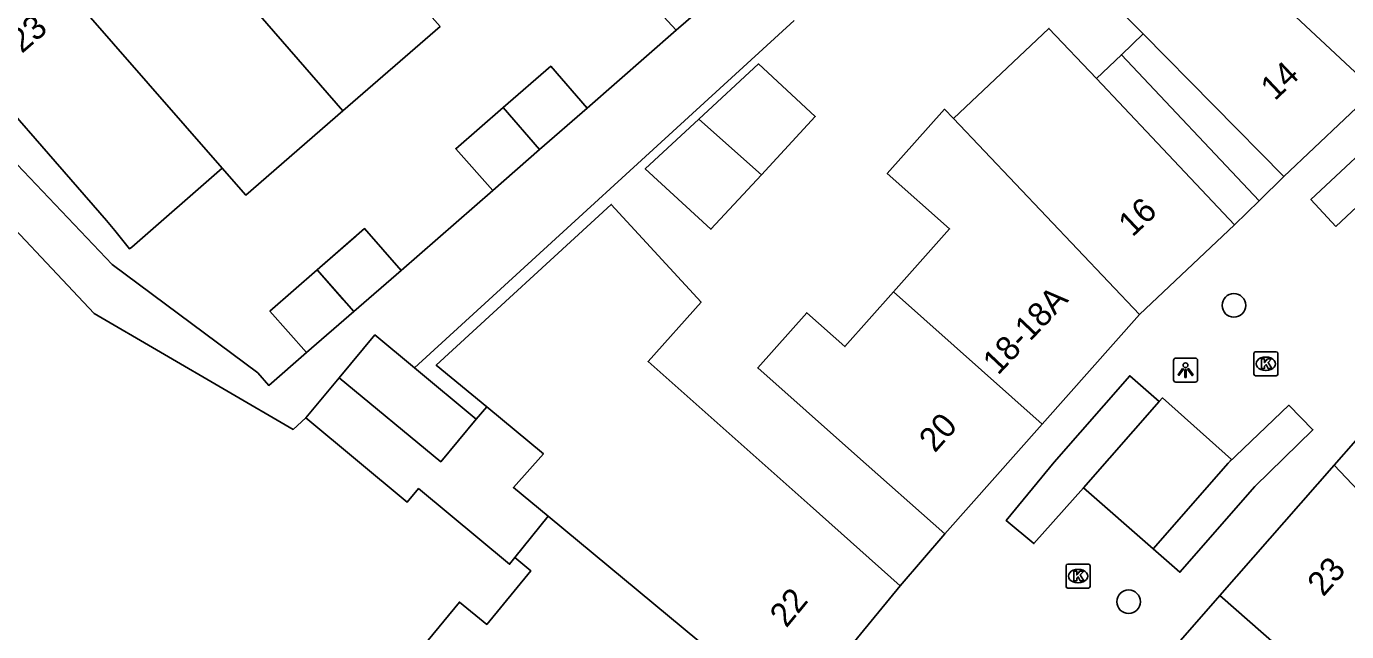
# Model space of a CAD drawing. Extents: x 161882 to 162509, y 381687 to 382379.
# Drawn here: x 162050.8 to 162105.6, y 382066.2 to 382091.3 of the extents above; entities that cross this region are included whole.
import ezdxf

# ---------------------------------------------------------------- set-up
doc = ezdxf.new("R2010")
doc.units = 0
for name, color, linetype in [('IMGEO_Boom', 7, 'Continuous'), ('IMGEO_Kolk', 7, 'Continuous'), ('IMGEO_Lichtpunt', 7, 'Continuous'), ('IMGEO_Pand', 7, 'Continuous'), ('IMGEO_Pand_nummerreeks', 7, 'Continuous'), ('IMGEO_Pand_overbouw', 7, 'Continuous'), ('IMGEO_Pand_vergunning_verleend', 7, 'Continuous'), ('IMGEO_Voetpad_open', 7, 'Continuous'), ('IMGEO_Woonerf_open', 7, 'Continuous')]:
    doc.layers.add(name, color=color, linetype=linetype)

msp = doc.modelspace()

# ---------------------------------------------------------------- linework, layer by layer
at = {"layer": 'IMGEO_Boom'}
for centre in [(162100.899, 382079.754), (162096.533, 382067.465)]:
    msp.add_circle(centre, 0.489, dxfattribs=at)
at = {"layer": 'IMGEO_Kolk'}
for p, q in [((162101.724, 382076.906), (162101.724, 382077.758)), ((162101.799, 382077.832), (162102.651, 382077.832)), ((162102.212, 382077.612), (162102.237, 382077.612)), ((162102.725, 382077.758), (162102.725, 382076.906)), ((162102.235, 382077.052), (162102.21, 382077.052)), ((162102.651, 382076.832), (162101.799, 382076.832)), ((162093.935, 382068.1), (162093.935, 382068.952)), ((162094.01, 382069.026), (162094.862, 382069.026)), ((162094.423, 382068.806), (162094.448, 382068.806)), ((162094.936, 382068.952), (162094.936, 382068.1)), ((162094.446, 382068.246), (162094.421, 382068.246)), ((162094.862, 382068.026), (162094.01, 382068.026))]:
    msp.add_line(p, q, dxfattribs=at)
for points in [[(162101.724, 382076.906), (162101.724, 382077.758)], [(162101.799, 382077.832), (162102.651, 382077.832)], [(162102.045, 382077.532), (162102.168, 382077.532), (162102.168, 382077.381), (162102.298, 382077.532), (162102.462, 382077.532), (162102.316, 382077.381), (162102.469, 382077.132), (162102.317, 382077.132), (162102.232, 382077.296), (162102.168, 382077.229), (162102.168, 382077.132), (162102.045, 382077.132), (162102.045, 382077.532)], [(162102.725, 382077.758), (162102.725, 382076.906)], [(162102.651, 382076.832), (162101.799, 382076.832)], [(162093.935, 382068.1), (162093.935, 382068.952)], [(162094.01, 382069.026), (162094.862, 382069.026)], [(162094.256, 382068.726), (162094.379, 382068.726), (162094.379, 382068.575), (162094.509, 382068.726), (162094.673, 382068.726), (162094.527, 382068.575), (162094.68, 382068.326), (162094.528, 382068.326), (162094.443, 382068.49), (162094.379, 382068.423), (162094.379, 382068.326), (162094.256, 382068.326), (162094.256, 382068.726)], [(162094.936, 382068.952), (162094.936, 382068.1)], [(162094.862, 382068.026), (162094.01, 382068.026)]]:
    msp.add_lwpolyline(points, dxfattribs=at)
for centre, start, end in [((162101.801, 382077.756), 91.552, 178.448), ((162101.801, 382077.756), 91.552, 178.448), ((162102.649, 382077.756), 1.552, 88.448), ((162102.649, 382077.756), 1.552, 88.448), ((162101.801, 382076.908), 181.552, 268.448), ((162101.801, 382076.908), 181.552, 268.448), ((162102.649, 382076.908), 271.552, 358.448), ((162102.649, 382076.908), 271.552, 358.448), ((162094.012, 382068.95), 91.552, 178.448), ((162094.012, 382068.95), 91.552, 178.448), ((162094.86, 382068.95), 1.552, 88.448), ((162094.86, 382068.95), 1.552, 88.448), ((162094.012, 382068.102), 181.552, 268.448), ((162094.012, 382068.102), 181.552, 268.448), ((162094.86, 382068.102), 271.552, 358.448), ((162094.86, 382068.102), 271.552, 358.448)]:
    msp.add_arc(centre, 0.0765, start, end, dxfattribs=at)
for centre, major_axis, ratio, start_param, end_param in [((162102.211, 382077.332), (-0.387, 0.002), 0.722429, 4.712389, 7.853982), ((162102.236, 382077.332), (-0.39, 0.002), 0.717154, 1.570796, 4.712389), ((162094.422, 382068.526), (-0.387, 0.002), 0.722429, 4.712389, 7.853982), ((162094.447, 382068.526), (-0.39, 0.002), 0.717154, 1.570796, 4.712389)]:
    msp.add_ellipse(centre, major_axis=major_axis, ratio=ratio, start_param=start_param, end_param=end_param, dxfattribs=at)
at = {"layer": 'IMGEO_Lichtpunt'}
for p, q in [((162098.394, 382077.472), (162098.394, 382076.665)), ((162098.394, 382077.472), (162098.394, 382076.665)), ((162099.296, 382077.567), (162098.488, 382077.567)), ((162099.296, 382077.567), (162098.488, 382077.567)), ((162099.39, 382076.665), (162099.39, 382077.472)), ((162099.39, 382076.665), (162099.39, 382077.472)), ((162098.488, 382076.571), (162099.296, 382076.571)), ((162098.488, 382076.571), (162099.296, 382076.571))]:
    msp.add_line(p, q, dxfattribs=at)
for points in [[(162098.768, 382077.136), (162098.807, 382077.108), (162098.619, 382076.846), (162098.581, 382076.873), (162098.768, 382077.136)], [(162098.87, 382077.088), (162098.917, 382077.088), (162098.917, 382076.766), (162098.87, 382076.766), (162098.87, 382077.088)], [(162098.98, 382077.108), (162099.018, 382077.135), (162099.205, 382076.873), (162099.166, 382076.845), (162098.98, 382077.108)]]:
    msp.add_lwpolyline(points, dxfattribs=at)
msp.add_circle((162098.893, 382077.27), 0.0994, dxfattribs=at)
for centre, start, end in [((162098.488, 382077.472), 90, 180), ((162098.488, 382077.472), 90, 180), ((162099.296, 382077.472), 0, 90), ((162099.296, 382077.472), 0, 90), ((162098.488, 382076.665), 180, 270), ((162098.488, 382076.665), 180, 270), ((162099.296, 382076.665), 270, 0), ((162099.296, 382076.665), 270, 360)]:
    msp.add_arc(centre, 0.0946, start, end, dxfattribs=at)
at = {"layer": 'IMGEO_Pand'}
for points in [[(162055.4, 382097.641), (162063.941, 382087.819)], [(162097.513, 382097.25), (162094.202, 382093.977), (162097.133, 382091.008), (162102.969, 382085.099)], [(162077.765, 382091.172), (162076.207, 382092.866), (162078.156, 382094.66), (162079.764, 382092.912)], [(162058.933, 382085.442), (162055.177, 382082.169), (162055.093, 382082.095), (162054.473, 382082.858), (162054.137, 382083.272), (162047.556, 382090.818), (162051.36, 382094.127)], [(162051.36, 382094.127), (162058.933, 382085.442)], [(162079.764, 382092.912), (162077.765, 382091.172)], [(162066.981, 382092.451), (162067.968, 382091.321), (162063.941, 382087.819)], [(162103.466, 382091.714), (162106.745, 382088.664)], [(162100.923, 382083.091), (162097.49, 382086.726), (162095.194, 382089.156), (162093.223, 382091.242), (162089.263, 382087.5)], [(162070.588, 382087.957), (162072.56, 382089.667), (162074.071, 382087.926)], [(162078.71, 382087.476), (162081.182, 382089.764), (162083.536, 382087.585), (162081.303, 382085.172)], [(162106.745, 382088.664), (162102.969, 382085.099)], [(162063.941, 382087.819), (162059.914, 382084.317), (162058.933, 382085.442)], [(162070.152, 382084.523), (162068.617, 382086.246), (162070.588, 382087.957)], [(162072.1, 382086.214), (162070.588, 382087.957)], [(162074.071, 382087.926), (162072.1, 382086.214)], [(162089.263, 382087.5), (162088.893, 382087.889), (162086.522, 382085.22), (162089.102, 382082.927), (162086.776, 382080.309)], [(162081.303, 382085.172), (162079.207, 382082.908), (162076.484, 382085.416), (162078.71, 382087.476)], [(162081.303, 382085.172), (162078.71, 382087.476)], [(162089.263, 382087.5), (162096.989, 382079.376)], [(162072.1, 382086.214), (162070.152, 382084.523)], [(162069.907, 382075.539), (162067.809, 382077.272), (162075.073, 382083.943), (162078.794, 382079.892), (162076.599, 382077.421), (162083.323, 382071.448), (162087.06, 382068.127)], [(162062.876, 382081.227), (162064.84, 382082.941), (162066.352, 382081.201)], [(162100.923, 382083.091), (162096.989, 382079.376)], [(162062.431, 382077.793), (162060.912, 382079.512), (162062.876, 382081.227)], [(162062.876, 382081.227), (162064.388, 382079.494)], [(162066.352, 382081.201), (162064.388, 382079.494)], [(162088.904, 382070.275), (162085.161, 382073.6), (162081.15, 382077.162), (162083.182, 382079.449), (162084.764, 382078.044), (162086.776, 382080.309)], [(162086.776, 382080.309), (162092.947, 382074.826)], [(162064.388, 382079.494), (162062.431, 382077.793)], [(162096.989, 382079.376), (162092.947, 382074.826)], [(162063.784, 382076.746), (162065.264, 382078.525), (162066.905, 382077.16)], [(162105.057, 382073.126), (162105.957, 382074.153), (162109.951, 382077.948)], [(162066.905, 382077.16), (162069.466, 382075.03)], [(162062.408, 382075.091), (162063.784, 382076.746)], [(162069.466, 382075.03), (162067.999, 382073.266), (162063.784, 382076.746)], [(162069.466, 382075.03), (162069.907, 382075.539)], [(162069.907, 382075.539), (162072.259, 382073.596), (162071.012, 382072.194), (162072.448, 382071.006)], [(162071.071, 382069.292), (162070.851, 382069.018), (162067.077, 382072.157), (162066.61, 382071.596), (162062.408, 382075.091)], [(162092.947, 382074.826), (162088.904, 382070.275)], [(162100.315, 382067.715), (162105.057, 382073.126)], [(162105.057, 382073.126), (162110.296, 382067.596), (162110.143, 382067.255)], [(162072.448, 382071.006), (162071.071, 382069.292)], [(162072.448, 382071.006), (162078.704, 382065.833), (162082.558, 382062.647)], [(162066.827, 382065.081), (162068.774, 382067.448), (162069.903, 382066.519), (162071.74, 382068.742), (162071.071, 382069.292)], [(162087.06, 382068.127), (162082.558, 382062.647)], [(162096.374, 382063.219), (162100.315, 382067.715)], [(162100.315, 382067.715), (162108.591, 382060.467)]]:
    msp.add_lwpolyline(points, dxfattribs=at)
at = {"layer": 'IMGEO_Pand_overbouw'}
for points in [[(162097.133, 382091.009), (162096.23, 382090.146), (162101.946, 382084.095), (162102.969, 382085.099)], [(162095.194, 382089.156), (162097.49, 382086.726), (162100.923, 382083.091), (162101.946, 382084.095), (162096.23, 382090.146)]]:
    msp.add_lwpolyline(points, close=True, dxfattribs=at)
at = {"layer": 'IMGEO_Pand_vergunning_verleend'}
msp.add_lwpolyline([(162063.921, 382080.029), (162062.876, 382081.227), (162064.461, 382082.61), (162064.84, 382082.941), (162066.352, 382081.201), (162064.388, 382079.494), (162063.921, 382080.029)], dxfattribs=at)
at = {"layer": 'IMGEO_Voetpad_open'}
for points in [[(162045.016, 382091.412), (162046.474, 382089.736), (162054.365, 382081.454), (162060.406, 382076.959), (162060.864, 382076.431), (162062.431, 382077.793)], [(162066.905, 382077.16), (162082.663, 382091.572)], [(162074.071, 382087.926), (162077.765, 382091.172)], [(162062.408, 382075.091), (162061.871, 382074.611), (162053.625, 382079.413), (162043.519, 382090.148)], [(162066.352, 382081.201), (162070.152, 382084.523)]]:
    msp.add_lwpolyline(points, dxfattribs=at)
at = {"layer": 'IMGEO_Woonerf_open'}
for points in [[(162105.131, 382083.031), (162104.095, 382084.139), (162107.593, 382087.41), (162108.629, 382086.302), (162105.131, 382083.031)], [(162102.969, 382085.099), (162101.946, 382084.095), (162100.923, 382083.091)], [(162094.663, 382072.186), (162092.606, 382069.877), (162091.45, 382070.832), (162093.443, 382073.255), (162096.582, 382076.836), (162097.802, 382075.767)], [(162094.663, 382072.186), (162097.802, 382075.767)], [(162097.802, 382075.767), (162097.935, 382075.916), (162100.795, 382073.359), (162100.662, 382073.21)], [(162100.662, 382073.21), (162103.176, 382075.611), (162104.176, 382074.594), (162101.774, 382072.235), (162098.662, 382068.683), (162097.549, 382069.658)], [(162100.662, 382073.21), (162097.549, 382069.658)], [(162097.549, 382069.658), (162094.663, 382072.186)], [(162088.904, 382070.275), (162087.06, 382068.127)]]:
    msp.add_lwpolyline(points, dxfattribs=at)

# ---------------------------------------------------------------- texts
at = {"layer": 'IMGEO_Pand_nummerreeks'}
for s, rotation, p in [('23', 40.8175, (162050.623, 382090.176)), ('14', 43.3557, (162102.592, 382088.208)), ('16', 43.3614, (162096.691, 382082.56)), ('18-18A', 46.5757, (162091.114, 382076.829)), ('20', 48.3833, (162088.494, 382073.609)), ('23', 48.7678, (162104.608, 382067.638)), ('22', 50.5979, (162082.335, 382066.346))]:
    msp.add_text(s, height=1, rotation=rotation, dxfattribs=at).set_placement(p)

doc.saveas('drawing.dxf')
